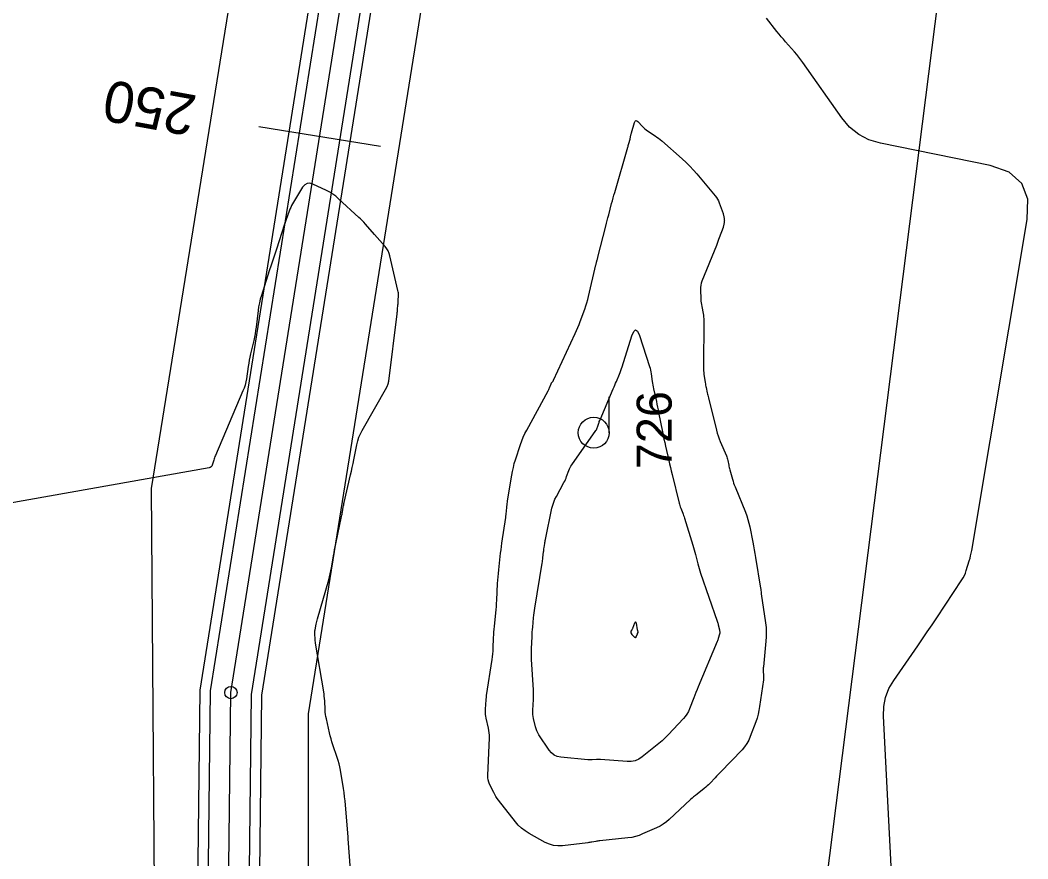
# Model space of a CAD drawing. Extents: x -534481 to -534256, y -1190577 to -1190138.
# Drawn here: x -534356.7 to -534332.21, y -1190332.36 to -1190311.98 of the extents above; entities that cross this region are included whole.
import ezdxf

# ---------------------------------------------------------------- set-up
doc = ezdxf.new("R2010")
doc.units = 0
for name, color, linetype in [('0_kroužky', 7, 'Continuous'), ('30', 7, 'Continuous'), ('31', 7, 'Continuous'), ('_N_osa', 7, 'Continuous'), ('_N_tenká', 7, 'Continuous'), ('_N_text', 7, 'Continuous'), ('Hranice parcel', 7, 'Continuous'), ('Parcelní čísla', 7, 'Continuous'), ('Značky kultur', 7, 'Continuous')]:
    doc.layers.add(name, color=color, linetype=linetype)

msp = doc.modelspace()

# ---------------------------------------------------------------- linework, layer by layer
at = {"layer": '0_kroužky'}
msp.add_circle((-534351.577, -1190328.316), 0.15, dxfattribs=at)
msp.add_circle((-534351.577, -1190328.316), 0.15, dxfattribs=at)
msp.add_circle((-534351.577, -1190328.316), 0.15, dxfattribs=at)
msp.add_circle((-534351.577, -1190328.316), 0.15, dxfattribs=at)
msp.add_circle((-534351.577, -1190328.316), 0.15, dxfattribs=at)
msp.add_circle((-534351.577, -1190328.316), 0.15, dxfattribs=at)
at = {"layer": '30'}
for points in [[(-534343.631, -1190332.041), (-534343.736, -1190332.029), (-534343.839, -1190332), (-534343.938, -1190331.955), (-534344.331, -1190331.737), (-534344.425, -1190331.678), (-534344.512, -1190331.611), (-534344.593, -1190331.536), (-534344.665, -1190331.452), (-534345.074, -1190330.933), (-534345.108, -1190330.888), (-534345.138, -1190330.841), (-534345.167, -1190330.793), (-534345.192, -1190330.743), (-534345.29, -1190330.541), (-534345.31, -1190330.489), (-534345.325, -1190330.437), (-534345.332, -1190330.383), (-534345.334, -1190330.327), (-534345.296, -1190329.412), (-534345.296, -1190329.354), (-534345.299, -1190329.297), (-534345.306, -1190329.24), (-534345.317, -1190329.183), (-534345.375, -1190328.934), (-534345.384, -1190328.889), (-534345.389, -1190328.844), (-534345.391, -1190328.799), (-534345.391, -1190328.753), (-534345.381, -1190328.57), (-534345.378, -1190328.524), (-534345.374, -1190328.478), (-534345.369, -1190328.433), (-534345.363, -1190328.387), (-534345.23, -1190327.509), (-534345.221, -1190327.443), (-534345.214, -1190327.377), (-534345.208, -1190327.311), (-534345.205, -1190327.244), (-534345.194, -1190326.978), (-534345.19, -1190326.911), (-534345.186, -1190326.845), (-534345.181, -1190326.778), (-534345.175, -1190326.712), (-534345.141, -1190326.381), (-534345.134, -1190326.304), (-534345.127, -1190326.227), (-534345.122, -1190326.149), (-534345.117, -1190326.072), (-534345.096, -1190325.664), (-534345.091, -1190325.582), (-534345.085, -1190325.5), (-534345.078, -1190325.418), (-534345.069, -1190325.336), (-534345.032, -1190325.008), (-534345.023, -1190324.926), (-534345.013, -1190324.845), (-534345.002, -1190324.763), (-534344.99, -1190324.681), (-534344.9, -1190324.058), (-534344.895, -1190324.025), (-534344.891, -1190323.991), (-534344.887, -1190323.958), (-534344.884, -1190323.925), (-534344.871, -1190323.79), (-534344.867, -1190323.757), (-534344.863, -1190323.724), (-534344.858, -1190323.69), (-534344.853, -1190323.657), (-534344.753, -1190323.036), (-534344.735, -1190322.941), (-534344.714, -1190322.846), (-534344.69, -1190322.753), (-534344.662, -1190322.66), (-534344.542, -1190322.29), (-534344.51, -1190322.199), (-534344.474, -1190322.109), (-534344.433, -1190322.021), (-534344.388, -1190321.935), (-534343.866, -1190320.983), (-534343.857, -1190320.965), (-534343.848, -1190320.947), (-534343.84, -1190320.929), (-534343.832, -1190320.911), (-534343.795, -1190320.817), (-534343.792, -1190320.808), (-534343.787, -1190320.8), (-534343.783, -1190320.792), (-534343.777, -1190320.784), (-534343.754, -1190320.754), (-534343.749, -1190320.746), (-534343.744, -1190320.738), (-534343.739, -1190320.73), (-534343.735, -1190320.722), (-534343.209, -1190319.591), (-534343.176, -1190319.518), (-534343.145, -1190319.444), (-534343.115, -1190319.37), (-534343.087, -1190319.295), (-534342.978, -1190318.995), (-534342.952, -1190318.919), (-534342.928, -1190318.843), (-534342.907, -1190318.766), (-534342.887, -1190318.689), (-534342.706, -1190317.92), (-534342.702, -1190317.905), (-534342.698, -1190317.889), (-534342.694, -1190317.874), (-534342.69, -1190317.858), (-534342.673, -1190317.797), (-534342.669, -1190317.781), (-534342.665, -1190317.766), (-534342.661, -1190317.751), (-534342.657, -1190317.735), (-534342.468, -1190316.982), (-534342.45, -1190316.913), (-534342.433, -1190316.845), (-534342.415, -1190316.776), (-534342.397, -1190316.708), (-534342.326, -1190316.434), (-534342.308, -1190316.366), (-534342.29, -1190316.297), (-534342.271, -1190316.229), (-534342.251, -1190316.161), (-534341.933, -1190315.065), (-534341.926, -1190315.043), (-534341.92, -1190315.021), (-534341.914, -1190314.999), (-534341.908, -1190314.977), (-534341.879, -1190314.871), (-534341.875, -1190314.858), (-534341.872, -1190314.844), (-534341.869, -1190314.831), (-534341.866, -1190314.818), (-534341.856, -1190314.764), (-534341.853, -1190314.75), (-534341.85, -1190314.737), (-534341.846, -1190314.724), (-534341.843, -1190314.711), (-534341.767, -1190314.461), (-534341.753, -1190314.43), (-534341.735, -1190314.417), (-534341.713, -1190314.421), (-534341.687, -1190314.442), (-534341.575, -1190314.561), (-534341.546, -1190314.59), (-534341.516, -1190314.617), (-534341.484, -1190314.642), (-534341.451, -1190314.666), (-534341.267, -1190314.789), (-534341.226, -1190314.817), (-534341.185, -1190314.847), (-534341.146, -1190314.879), (-534341.107, -1190314.911), (-534340.608, -1190315.35), (-534340.514, -1190315.436), (-534340.424, -1190315.525), (-534340.337, -1190315.618), (-534340.253, -1190315.714), (-534339.809, -1190316.242), (-534339.778, -1190316.282), (-534339.751, -1190316.325), (-534339.728, -1190316.37), (-534339.709, -1190316.417), (-534339.618, -1190316.675), (-534339.613, -1190316.692), (-534339.608, -1190316.708), (-534339.604, -1190316.725), (-534339.601, -1190316.742), (-534339.589, -1190316.811), (-534339.587, -1190316.828), (-534339.586, -1190316.844), (-534339.587, -1190316.861), (-534339.59, -1190316.878), (-534339.602, -1190316.946), (-534339.605, -1190316.963), (-534339.609, -1190316.98), (-534339.614, -1190316.996), (-534339.619, -1190317.012), (-534339.709, -1190317.262), (-534339.726, -1190317.309), (-534339.744, -1190317.356), (-534339.762, -1190317.403), (-534339.781, -1190317.449), (-534340.131, -1190318.317), (-534340.149, -1190318.367), (-534340.16, -1190318.418), (-534340.167, -1190318.47), (-534340.167, -1190318.523), (-534340.158, -1190318.757), (-534340.155, -1190318.801), (-534340.151, -1190318.844), (-534340.145, -1190318.887), (-534340.137, -1190318.931), (-534340.104, -1190319.103), (-534340.097, -1190319.146), (-534340.091, -1190319.189), (-534340.088, -1190319.233), (-534340.088, -1190319.276), (-534340.093, -1190320.406), (-534340.092, -1190320.45), (-534340.09, -1190320.494), (-534340.086, -1190320.538), (-534340.081, -1190320.582), (-534340.053, -1190320.782), (-534340.048, -1190320.813), (-534340.043, -1190320.844), (-534340.037, -1190320.875), (-534340.031, -1190320.906), (-534340.004, -1190321.03), (-534339.997, -1190321.061), (-534339.99, -1190321.092), (-534339.983, -1190321.122), (-534339.975, -1190321.153), (-534339.778, -1190321.939), (-534339.759, -1190322.01), (-534339.738, -1190322.079), (-534339.713, -1190322.147), (-534339.686, -1190322.215), (-534339.538, -1190322.563), (-534339.527, -1190322.59), (-534339.518, -1190322.617), (-534339.51, -1190322.645), (-534339.504, -1190322.674), (-534339.481, -1190322.788), (-534339.475, -1190322.816), (-534339.468, -1190322.844), (-534339.461, -1190322.872), (-534339.454, -1190322.901), (-534339.39, -1190323.129), (-534339.376, -1190323.176), (-534339.361, -1190323.223), (-534339.344, -1190323.269), (-534339.327, -1190323.315), (-534339.076, -1190323.932), (-534339.043, -1190324.02), (-534339.014, -1190324.109), (-534338.989, -1190324.199), (-534338.969, -1190324.291), (-534338.897, -1190324.66), (-534338.88, -1190324.752), (-534338.863, -1190324.845), (-534338.846, -1190324.937), (-534338.83, -1190325.03), (-534338.705, -1190325.779), (-534338.703, -1190325.791), (-534338.701, -1190325.802), (-534338.7, -1190325.814), (-534338.699, -1190325.825), (-534338.695, -1190325.872), (-534338.694, -1190325.883), (-534338.692, -1190325.895), (-534338.691, -1190325.906), (-534338.689, -1190325.918), (-534338.587, -1190326.621), (-534338.574, -1190326.733), (-534338.568, -1190326.845), (-534338.569, -1190326.957), (-534338.576, -1190327.07), (-534338.638, -1190327.692), (-534338.64, -1190327.718), (-534338.641, -1190327.745), (-534338.641, -1190327.771), (-534338.64, -1190327.797), (-534338.635, -1190327.903), (-534338.634, -1190327.929), (-534338.635, -1190327.955), (-534338.636, -1190327.982), (-534338.639, -1190328.008), (-534338.729, -1190328.654), (-534338.745, -1190328.749), (-534338.765, -1190328.842), (-534338.791, -1190328.934), (-534338.822, -1190329.024), (-534338.957, -1190329.384), (-534338.994, -1190329.471), (-534339.04, -1190329.554), (-534339.094, -1190329.631), (-534339.156, -1190329.703), (-534339.678, -1190330.247), (-534339.711, -1190330.281), (-534339.743, -1190330.315), (-534339.775, -1190330.349), (-534339.807, -1190330.383), (-534339.935, -1190330.52), (-534339.968, -1190330.553), (-534340.002, -1190330.585), (-534340.037, -1190330.616), (-534340.074, -1190330.645), (-534340.25, -1190330.78), (-534340.291, -1190330.813), (-534340.332, -1190330.846), (-534340.371, -1190330.881), (-534340.41, -1190330.916), (-534340.926, -1190331.398), (-534340.996, -1190331.459), (-534341.071, -1190331.512), (-534341.15, -1190331.56), (-534341.233, -1190331.601), (-534341.573, -1190331.751), (-534341.659, -1190331.785), (-534341.747, -1190331.812), (-534341.837, -1190331.833), (-534341.928, -1190331.846), (-534342.616, -1190331.919), (-534342.64, -1190331.921), (-534342.664, -1190331.925), (-534342.688, -1190331.928), (-534342.712, -1190331.932), (-534342.808, -1190331.949), (-534342.832, -1190331.953), (-534342.856, -1190331.956), (-534342.88, -1190331.96), (-534342.904, -1190331.963), (-534343.521, -1190332.037)], [(-534341.739, -1190326.977), (-534341.746, -1190326.981), (-534341.753, -1190326.98), (-534341.762, -1190326.974), (-534341.804, -1190326.936), (-534341.811, -1190326.928), (-534341.818, -1190326.92), (-534341.824, -1190326.911), (-534341.829, -1190326.902), (-534341.849, -1190326.863), (-534341.853, -1190326.854), (-534341.854, -1190326.845), (-534341.852, -1190326.835), (-534341.848, -1190326.826), (-534341.828, -1190326.789), (-534341.823, -1190326.779), (-534341.818, -1190326.77), (-534341.814, -1190326.76), (-534341.81, -1190326.75), (-534341.762, -1190326.622), (-534341.753, -1190326.604), (-534341.745, -1190326.598), (-534341.739, -1190326.605), (-534341.733, -1190326.625), (-534341.702, -1190326.79), (-534341.699, -1190326.801), (-534341.696, -1190326.812), (-534341.69, -1190326.834), (-534341.689, -1190326.839), (-534341.689, -1190326.844), (-534341.689, -1190326.849), (-534341.691, -1190326.854), (-534341.701, -1190326.879), (-534341.707, -1190326.894), (-534341.734, -1190326.967)]]:
    msp.add_lwpolyline(points, close=True, dxfattribs=at)
msp.add_lwpolyline([(-534348.67, -1190332.619), (-534348.725, -1190331.87), (-534348.726, -1190331.857), (-534348.727, -1190331.832), (-534348.727, -1190331.82), (-534348.792, -1190331.047), (-534348.801, -1190330.946), (-534348.813, -1190330.845), (-534348.826, -1190330.745), (-534348.842, -1190330.644), (-534348.916, -1190330.201), (-534348.931, -1190330.123), (-534348.948, -1190330.045), (-534348.969, -1190329.969), (-534348.993, -1190329.893), (-534349.098, -1190329.585), (-534349.122, -1190329.513), (-534349.143, -1190329.439), (-534349.163, -1190329.366), (-534349.181, -1190329.291), (-534349.257, -1190328.952), (-534349.268, -1190328.898), (-534349.276, -1190328.844), (-534349.283, -1190328.789), (-534349.287, -1190328.735), (-534349.298, -1190328.515), (-534349.302, -1190328.46), (-534349.307, -1190328.406), (-534349.314, -1190328.351), (-534349.322, -1190328.297), (-534349.518, -1190327.114), (-534349.522, -1190327.087), (-534349.526, -1190327.06), (-534349.528, -1190327.034), (-534349.53, -1190327.007), (-534349.538, -1190326.899), (-534349.538, -1190326.872), (-534349.537, -1190326.845), (-534349.535, -1190326.818), (-534349.53, -1190326.791), (-534349.502, -1190326.653), (-534349.495, -1190326.622), (-534349.487, -1190326.59), (-534349.479, -1190326.559), (-534349.471, -1190326.527), (-534349.199, -1190325.572), (-534349.18, -1190325.5), (-534349.163, -1190325.428), (-534349.147, -1190325.356), (-534349.134, -1190325.283), (-534349.084, -1190324.991), (-534349.071, -1190324.918), (-534349.058, -1190324.845), (-534349.044, -1190324.772), (-534349.029, -1190324.699), (-534348.888, -1190324.034), (-534348.883, -1190324.006), (-534348.877, -1190323.978), (-534348.872, -1190323.95), (-534348.866, -1190323.921), (-534348.846, -1190323.808), (-534348.841, -1190323.78), (-534348.836, -1190323.752), (-534348.83, -1190323.723), (-534348.823, -1190323.695), (-534348.67, -1190323.028), (-534348.649, -1190322.936), (-534348.629, -1190322.844), (-534348.61, -1190322.752), (-534348.591, -1190322.66), (-534348.517, -1190322.292), (-534348.495, -1190322.201), (-534348.466, -1190322.113), (-534348.43, -1190322.028), (-534348.387, -1190321.945), (-534347.792, -1190320.898), (-534347.789, -1190320.893), (-534347.787, -1190320.888), (-534347.784, -1190320.882), (-534347.782, -1190320.877), (-534347.772, -1190320.85), (-534347.766, -1190320.834), (-534347.75, -1190320.787), (-534347.747, -1190320.777), (-534347.744, -1190320.767), (-534347.742, -1190320.757), (-534347.741, -1190320.747), (-534347.538, -1190319.109), (-534347.535, -1190319.083), (-534347.532, -1190319.056), (-534347.529, -1190319.03), (-534347.526, -1190319.003), (-534347.517, -1190318.897), (-534347.515, -1190318.871), (-534347.513, -1190318.844), (-534347.512, -1190318.818), (-534347.51, -1190318.791), (-534347.505, -1190318.664), (-534347.505, -1190318.635), (-534347.507, -1190318.605), (-534347.511, -1190318.575), (-534347.517, -1190318.546), (-534347.714, -1190317.704), (-534347.732, -1190317.643), (-534347.757, -1190317.585), (-534347.789, -1190317.531), (-534347.829, -1190317.48), (-534348.085, -1190317.186), (-534348.309, -1190316.93), (-534348.346, -1190316.888), (-534348.385, -1190316.847), (-534348.425, -1190316.807), (-534348.467, -1190316.768), (-534348.959, -1190316.314), (-534349.027, -1190316.256), (-534349.099, -1190316.204), (-534349.175, -1190316.158), (-534349.254, -1190316.117), (-534349.586, -1190315.962), (-534349.66, -1190315.939), (-534349.727, -1190315.944), (-534349.784, -1190315.977), (-534349.834, -1190316.037), (-534350.056, -1190316.397), (-534350.081, -1190316.439), (-534350.103, -1190316.482), (-534350.124, -1190316.526), (-534350.142, -1190316.571), (-534350.212, -1190316.753), (-534350.229, -1190316.799), (-534350.246, -1190316.845), (-534350.262, -1190316.891), (-534350.277, -1190316.937), (-534350.473, -1190317.542), (-534350.52, -1190317.686), (-534350.597, -1190317.927), (-534350.644, -1190318.071), (-534350.836, -1190318.663), (-534350.863, -1190318.754), (-534350.886, -1190318.846), (-534350.904, -1190318.94), (-534350.917, -1190319.034), (-534350.966, -1190319.44), (-534350.977, -1190319.521), (-534350.99, -1190319.601), (-534351.005, -1190319.681), (-534351.023, -1190319.761), (-534351.1, -1190320.087), (-534351.117, -1190320.162), (-534351.132, -1190320.237), (-534351.145, -1190320.312), (-534351.157, -1190320.388), (-534351.202, -1190320.692), (-534351.216, -1190320.768), (-534351.234, -1190320.842), (-534351.257, -1190320.915), (-534351.285, -1190320.986), (-534351.955, -1190322.552), (-534351.966, -1190322.581), (-534351.977, -1190322.609), (-534351.987, -1190322.638), (-534351.996, -1190322.668), (-534352.029, -1190322.786), (-534352.041, -1190322.812), (-534352.057, -1190322.832), (-534352.079, -1190322.847), (-534352.107, -1190322.855), (-534363.252, -1190324.831)], dxfattribs=at)
at = {"layer": '31'}
msp.add_lwpolyline([(-534334.528, -1190352.171), (-534335.719, -1190328.886), (-534335.712, -1190328.653), (-534335.669, -1190328.431), (-534335.588, -1190328.219), (-534335.471, -1190328.018), (-534334.888, -1190327.182), (-534334.771, -1190327.013), (-534334.655, -1190326.843), (-534334.54, -1190326.673), (-534334.426, -1190326.502), (-534333.813, -1190325.578), (-534333.78, -1190325.525), (-534333.751, -1190325.469), (-534333.727, -1190325.412), (-534333.707, -1190325.352), (-534333.634, -1190325.111), (-534333.616, -1190325.05), (-534333.601, -1190324.989), (-534333.588, -1190324.928), (-534333.576, -1190324.866), (-534332.224, -1190316.817), (-534332.211, -1190316.326), (-534332.357, -1190315.943), (-534332.662, -1190315.669), (-534333.126, -1190315.505), (-534335.793, -1190314.964), (-534336.073, -1190314.881), (-534336.322, -1190314.751), (-534336.542, -1190314.575), (-534336.73, -1190314.352), (-534337.677, -1190313.007), (-534337.725, -1190312.941), (-534337.775, -1190312.876), (-534337.827, -1190312.812), (-534337.88, -1190312.75), (-534338.098, -1190312.504), (-534338.152, -1190312.442), (-534338.205, -1190312.379), (-534338.257, -1190312.315), (-534338.308, -1190312.251), (-534338.559, -1190311.929)], dxfattribs=at)
msp.add_lwpolyline([(-534341.665, -1190329.934), (-534341.754, -1190329.972), (-534341.849, -1190329.991), (-534341.95, -1190329.993), (-534342.595, -1190329.945), (-534342.62, -1190329.944), (-534342.646, -1190329.943), (-534342.672, -1190329.943), (-534342.697, -1190329.944), (-534342.8, -1190329.95), (-534342.825, -1190329.951), (-534342.851, -1190329.951), (-534342.877, -1190329.95), (-534342.902, -1190329.948), (-534343.56, -1190329.884), (-534343.646, -1190329.867), (-534343.723, -1190329.832), (-534343.789, -1190329.781), (-534343.845, -1190329.713), (-534344.093, -1190329.339), (-534344.119, -1190329.295), (-534344.142, -1190329.248), (-534344.16, -1190329.2), (-534344.174, -1190329.15), (-534344.221, -1190328.946), (-534344.231, -1190328.895), (-534344.237, -1190328.844), (-534344.24, -1190328.792), (-534344.239, -1190328.74), (-534344.226, -1190328.487), (-534344.224, -1190328.427), (-534344.223, -1190328.368), (-534344.224, -1190328.308), (-534344.227, -1190328.249), (-534344.27, -1190327.513), (-534344.273, -1190327.446), (-534344.274, -1190327.379), (-534344.274, -1190327.312), (-534344.272, -1190327.245), (-534344.26, -1190326.961), (-534344.257, -1190326.903), (-534344.253, -1190326.845), (-534344.249, -1190326.786), (-534344.243, -1190326.728), (-534344.22, -1190326.496), (-534344.214, -1190326.438), (-534344.206, -1190326.38), (-534344.198, -1190326.322), (-534344.19, -1190326.264), (-534344.012, -1190325.168), (-534344.007, -1190325.136), (-534344.003, -1190325.103), (-534343.999, -1190325.071), (-534343.995, -1190325.039), (-534343.979, -1190324.895), (-534343.976, -1190324.87), (-534343.973, -1190324.845), (-534343.969, -1190324.819), (-534343.966, -1190324.794), (-534343.951, -1190324.694), (-534343.947, -1190324.669), (-534343.943, -1190324.644), (-534343.938, -1190324.619), (-534343.933, -1190324.594), (-534343.775, -1190323.835), (-534343.756, -1190323.76), (-534343.732, -1190323.688), (-534343.703, -1190323.617), (-534343.669, -1190323.548), (-534343.484, -1190323.211), (-534343.466, -1190323.176), (-534343.449, -1190323.14), (-534343.433, -1190323.104), (-534343.419, -1190323.067), (-534343.365, -1190322.919), (-534343.35, -1190322.882), (-534343.333, -1190322.847), (-534343.313, -1190322.813), (-534343.292, -1190322.78), (-534342.706, -1190321.948), (-534342.693, -1190321.928), (-534342.682, -1190321.907), (-534342.673, -1190321.886), (-534342.665, -1190321.864), (-534342.639, -1190321.773), (-534342.632, -1190321.75), (-534342.625, -1190321.728), (-534342.616, -1190321.706), (-534342.607, -1190321.684), (-534342.285, -1190320.933), (-534342.266, -1190320.889), (-534342.247, -1190320.844), (-534342.228, -1190320.8), (-534342.21, -1190320.756), (-534342.135, -1190320.579), (-534342.117, -1190320.534), (-534342.1, -1190320.489), (-534342.084, -1190320.444), (-534342.069, -1190320.398), (-534341.831, -1190319.643), (-534341.787, -1190319.538), (-534341.742, -1190319.502), (-534341.697, -1190319.537), (-534341.652, -1190319.642), (-534341.406, -1190320.39), (-534341.392, -1190320.435), (-534341.381, -1190320.479), (-534341.372, -1190320.524), (-534341.364, -1190320.57), (-534341.339, -1190320.753), (-534341.332, -1190320.799), (-534341.324, -1190320.844), (-534341.316, -1190320.89), (-534341.306, -1190320.935), (-534341.239, -1190321.245), (-534341.224, -1190321.311), (-534341.21, -1190321.378), (-534341.196, -1190321.445), (-534341.183, -1190321.512), (-534341.089, -1190321.983), (-534341.072, -1190322.07), (-534341.054, -1190322.156), (-534341.035, -1190322.242), (-534341.016, -1190322.329), (-534340.936, -1190322.673), (-534340.916, -1190322.758), (-534340.896, -1190322.844), (-534340.876, -1190322.93), (-534340.855, -1190323.016), (-534340.686, -1190323.71), (-534340.678, -1190323.741), (-534340.669, -1190323.772), (-534340.658, -1190323.802), (-534340.647, -1190323.832), (-534340.599, -1190323.952), (-534340.588, -1190323.982), (-534340.577, -1190324.013), (-534340.566, -1190324.043), (-534340.556, -1190324.074), (-534340.351, -1190324.732), (-534340.333, -1190324.788), (-534340.317, -1190324.845), (-534340.302, -1190324.902), (-534340.287, -1190324.959), (-534340.23, -1190325.188), (-534340.215, -1190325.245), (-534340.199, -1190325.302), (-534340.181, -1190325.358), (-534340.163, -1190325.414), (-534339.758, -1190326.582), (-534339.751, -1190326.604), (-534339.744, -1190326.626), (-534339.738, -1190326.648), (-534339.733, -1190326.67), (-534339.705, -1190326.794), (-534339.703, -1190326.804), (-534339.701, -1190326.814), (-534339.698, -1190326.834), (-534339.698, -1190326.839), (-534339.697, -1190326.845), (-534339.697, -1190326.85), (-534339.698, -1190326.855), (-534339.7, -1190326.876), (-534339.7, -1190326.881), (-534339.701, -1190326.887), (-534339.702, -1190326.892), (-534339.704, -1190326.897), (-534339.733, -1190326.999), (-534339.738, -1190327.018), (-534339.744, -1190327.036), (-534339.751, -1190327.054), (-534339.758, -1190327.072), (-534340.222, -1190328.178), (-534340.249, -1190328.244), (-534340.276, -1190328.311), (-534340.303, -1190328.377), (-534340.329, -1190328.444), (-534340.432, -1190328.711), (-534340.46, -1190328.776), (-534340.495, -1190328.837), (-534340.535, -1190328.895), (-534340.582, -1190328.948), (-534340.954, -1190329.341), (-534341.026, -1190329.415), (-534341.101, -1190329.486), (-534341.178, -1190329.555), (-534341.258, -1190329.621), (-534341.581, -1190329.879)], close=True, dxfattribs=at)
at = {"layer": '_N_osa'}
msp.add_lwpolyline([(-534409.868, -1190391.439), (-534405.947, -1190382.816), (-534400.873, -1190377.487), (-534393.696, -1190372.718), (-534384.927, -1190365.477), (-534382.631, -1190361.148), (-534355.894, -1190347.823), (-534351.738, -1190342.389), (-534351.577, -1190328.316), (-534347.204, -1190300.921), (-534345.553, -1190283.64), (-534344.682, -1190264.494)], dxfattribs=at)
at = {"layer": '_N_tenká'}
for points in [[(-534409.916, -1190390.337), (-534406.368, -1190382.532), (-534401.196, -1190377.102), (-534393.995, -1190372.316), (-534385.322, -1190365.155), (-534382.997, -1190360.772), (-534356.221, -1190347.427), (-534352.236, -1190342.217), (-534352.076, -1190328.274), (-534347.7, -1190300.857), (-534346.052, -1190283.605), (-534345.255, -1190266.096)], [(-534409.879, -1190389.652), (-534406.578, -1190382.39), (-534401.358, -1190376.909), (-534394.144, -1190372.115), (-534385.52, -1190364.994), (-534383.181, -1190360.584), (-534356.384, -1190347.229), (-534352.485, -1190342.131), (-534352.326, -1190328.253), (-534347.948, -1190300.826), (-534346.301, -1190283.588), (-534345.507, -1190266.125)], [(-534409.363, -1190391.537), (-534405.527, -1190383.099), (-534400.549, -1190377.873), (-534393.398, -1190373.12), (-534384.532, -1190365.799), (-534382.264, -1190361.524), (-534355.568, -1190348.219), (-534351.24, -1190342.56), (-534351.077, -1190328.359), (-534346.708, -1190300.984), (-534345.054, -1190283.675), (-534344.256, -1190266.142)], [(-534409.111, -1190391.586), (-534405.317, -1190383.241), (-534400.388, -1190378.065), (-534393.249, -1190373.321), (-534384.335, -1190365.96), (-534382.081, -1190361.712), (-534355.404, -1190348.417), (-534350.991, -1190342.646), (-534350.828, -1190328.38), (-534346.46, -1190301.016), (-534344.805, -1190283.693), (-534344.008, -1190266.196)]]:
    msp.add_lwpolyline(points, dxfattribs=at)
at = {"layer": '_N_text'}
msp.add_lwpolyline([(-534347.939, -1190315.044), (-534350.902, -1190314.571)], dxfattribs=at)
at = {"layer": 'Hranice parcel'}
msp.add_line((-534333.95, -1190307.91), (-534337.65, -1190337.15), dxfattribs=at)
for points in [[(-534353.4, -1190337.34), (-534353.51, -1190323.36), (-534348.1, -1190289.81), (-534348.02, -1190285.43)], [(-534346.16, -1190306.72), (-534349.7, -1190328.83), (-534349.69, -1190337.24)]]:
    msp.add_lwpolyline(points, dxfattribs=at)
at = {"layer": 'Značky kultur'}
msp.add_line((-534342.386, -1190322.002), (-534342.386, -1190321.127), dxfattribs=at)
msp.add_circle((-534342.761, -1190322.002), 0.375, dxfattribs=at)

# ---------------------------------------------------------------- texts
at = {"layer": '_N_text'}
msp.add_text('250', height=1, rotation=169.7045, dxfattribs=at).set_placement((-534352.37, -1190313.816))
at = {"layer": 'Parcelní čísla'}
msp.add_text('726', height=0.85, rotation=90, dxfattribs=at).set_placement((-534340.867, -1190322.887))

doc.saveas('drawing.dxf')
